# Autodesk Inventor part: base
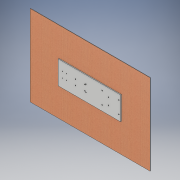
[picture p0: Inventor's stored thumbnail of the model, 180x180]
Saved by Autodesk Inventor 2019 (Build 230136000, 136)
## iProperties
Created: 2021-07
Part Number: base
Material: Generic
Document SubType Name: Modeling
Designer: Avinash
Density: 1 g/cm^3
Appearance: Default
Author: Avinash
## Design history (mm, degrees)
sketch "Sketch1"
  geometry: L1 (0, 0)-(-800, 0); L2 (-800, 0)-(-800, 300); L3 (-800, 300)-(0, 300); L4 (0, 300)-(0, 0)
  constraints: 8 end point, 2 parallel, 1 horizontal, 1 perpendicular
  dimensions: "d0" = 800 distance of L2.end L3.end; "d1" = 300 distance of L1.end L2.end
extrude "Extrusion1" new body sketch "Sketch1" distance "d2" = 10; taper "d3" = 0 deg
sketch "Sketch2"
  geometry: L1 (-30, 225)-(-20, 225); L2 (-20, 225)-(-20, 235); L3 (-20, 235)-(-30, 235); L4 (-30, 235)-(-30, 225); L5 (-30, 65)-(-20, 65); L6 (-20, 65)-(-20, 75); L7 (-20, 75)-(-30, 75); L8 (-30, 75)-(-30, 65); L9 (-800, 0)-(0, 0) reference; L10 (0, 0)-(0, 300) reference; L11 (0, 300)-(-800, 300) reference; L12 (-240, 225)-(-230, 225); L13 (-230, 225)-(-230, 235); L14 (-230, 235)-(-240, 235); L15 (-240, 235)-(-240, 225); L16 (-240, 65)-(-230, 65); L17 (-230, 65)-(-230, 75); L18 (-230, 75)-(-240, 75); L19 (-240, 75)-(-240, 65); L20 (-150, 200)-(-160, 200); L21 (-160, 200)-(-160, 190); L22 (-160, 190)-(-150, 190); L23 (-150, 190)-(-150, 200); L24 (-160, 110)-(-160, 100); L25 (-150, 100)-(-150, 110); L26 (-150, 110)-(-160, 110); L27 (-160, 100)-(-150, 100); L28 (-450, 110)-(-450, 100); L29 (-440, 100)-(-440, 110); L30 (-440, 110)-(-450, 110); L31 (-450, 100)-(-440, 100); L32 (-450, 200)-(-450, 190); L33 (-440, 190)-(-440, 200); L34 (-440, 200)-(-450, 200); L35 (-450, 190)-(-440, 190)
  constraints: 64 end point, 15 parallel, 8 horizontal, 8 perpendicular, 1 vertical
  dimensions: "d4" = 10 distance of L2.end L3.end; "d5" = 10 distance of L3.end L1.start; "d7" = 10 distance of L6.end L7.end; "d8" = 10 distance of L7.end L5.start; "d9" = 65 distance between parallel lines of L9 L5; "d10" = 20 distance between parallel lines of L10 L6; "d11" = 65 distance between parallel lines of L11 L3; "d12" = 10 distance of L13.end L14.end; "d13" = 10 distance of L14.end L12.start; "d14" = 65 distance between parallel lines of L11 L14; "d18" = 220 distance between parallel lines of L15 L2; "d19" = 20 distance between parallel lines of L10 L2; "d20" = 10 distance of L17.end L18.end; "d21" = 10 distance of L18.end L16.start; "d22" = 220 distance between parallel lines of L6 L19; "d23" = 65 distance between parallel lines of L9 L16; "d26" = 10 distance of L20.end L21.end; "d27" = 10 distance of L21.end L22.end; "d28" = 10 distance of L24.start L24.end; "d29" = 10 distance of L24.end L25.start; "d30" = 100 distance between parallel lines of L11 L20; "d31" = 100 distance between parallel lines of L9 L27; "d32" = 10 distance of L28.start L28.end; "d33" = 10 distance of L28.end L29.start; "d34" = 10 distance of L32.start L32.end; "d35" = 10 distance of L32.end L33.start; "d36" = 100 distance between parallel lines of L11 L34; "d37" = 100 distance between parallel lines of L9 L31; "d38" = 300 distance between parallel lines of L32 L23; "d39" = 300 distance between parallel lines of L28 L25; "d41" = 90 distance between parallel lines of L23 L15; "d42" = 90 distance between parallel lines of L25 L19
extrude "Extrusion2" cut sketch "Sketch2" distance "d24" = 50; taper "d25" = 0 deg
extrude "Extrusion3" cut sketch "Sketch2" distance "d43" = 50; taper "d44" = 0 deg
sketch "Sketch3"
  geometry: L1 (-575, 110)-(-585, 110); L2 (-585, 110)-(-585, 120); L3 (-585, 120)-(-575, 120); L4 (-575, 120)-(-575, 110); L5 (-575, 180)-(-585, 180); L6 (-585, 180)-(-585, 190); L7 (-585, 190)-(-575, 190); L8 (-575, 190)-(-575, 180); L9 (-800, 0)-(0, 0) reference; L10 (0, 300)-(-800, 300) reference; L11 (-455, 110)-(-465, 110); L12 (-465, 110)-(-465, 120); L13 (-465, 120)-(-455, 120); L14 (-455, 120)-(-455, 110); L15 (-455, 180)-(-465, 180); L16 (-465, 180)-(-465, 190); L17 (-465, 190)-(-455, 190); L18 (-455, 190)-(-455, 180); L19 (-450, 200)-(-450, 190) reference; L20 (-450, 110)-(-450, 100) reference
  constraints: 32 end point, 8 parallel, 4 horizontal, 4 perpendicular
  dimensions: "d48" = 10 distance of L2.end L3.end; "d49" = 10 distance of L6.end L7.end; "d50" = 10 distance of L5.end L6.end; "d58" = 10 distance of L3.end L1.start; "d60" = 10 distance of L12.end L13.end; "d61" = 10 distance of L13.end L11.start; "d62" = 110 distance between parallel lines of L11 L9; "d63" = 10 distance of L16.end L17.end; "d64" = 10 distance of L17.end L15.start; "d65" = 110 distance between parallel lines of L17 L10; "d66" = 5 distance between parallel lines of L19 L18; "d67" = 5 distance between parallel lines of L20 L14; "d68" = 110 distance between parallel lines of L10 L7; "d69" = 110 distance between parallel lines of L9 L1; "d70" = 130 distance between parallel lines of L6 L18; "d71" = 130 distance between parallel lines of L2 L14
extrude "Extrusion4" cut sketch "Sketch3" distance "d55" = 10; taper "d56" = 0 deg
sketch "Sketch4"
  geometry: L1 (700, 110)-(690, 110); L2 (690, 110)-(690, 115); L3 (690, 115)-(700, 115); L4 (700, 115)-(700, 110); L5 (700, 185)-(690, 185); L6 (690, 185)-(690, 190); L7 (690, 190)-(700, 190); L8 (700, 190)-(700, 185); L9 (750, 110)-(740, 110); L10 (740, 110)-(740, 115); L11 (740, 115)-(750, 115); L12 (750, 115)-(750, 110); L13 (750, 185)-(740, 185); L14 (740, 185)-(740, 190); L15 (740, 190)-(750, 190); L16 (750, 190)-(750, 185); L17 (0, 0)-(800, 0) reference; L18 (800, 300)-(0, 300) reference; L19 (800, 0)-(800, 300) reference
  constraints: 32 end point, 8 parallel, 4 horizontal, 4 perpendicular
  dimensions: "d72" = 5 distance of L1.end L2.end; "d73" = 10 distance of L1.start L1.end; "d74" = 5 distance of L5.end L6.end; "d75" = 10 distance of L5.start L5.end; "d76" = 5 distance of L9.end L10.end; "d77" = 10 distance of L9.start L9.end; "d78" = 5 distance of L13.end L14.end; "d79" = 10 distance of L13.start L13.end; "d80" = 110 distance between parallel lines of L17 L1; "d81" = 110 distance between parallel lines of L18 L7; "d82" = 110 distance between parallel lines of L18 L15; "d83" = 110 distance between parallel lines of L17 L9; "d84" = 60 distance between parallel lines of L2 L12; "d85" = 60 distance between parallel lines of L6 L16; "d90" = 50 distance between parallel lines of L19 L16; "d91" = 50 distance between parallel lines of L19 L12
extrude "Extrusion5" cut sketch "Sketch4" distance "d88" = 10; taper "d89" = 0 deg
sketch "Sketch5"
  geometry: L1 (800, 0)-(0, 0) reference; L2 (800, 0)-(0, 0); L3 (0, 0)-(0, 300); L4 (0, 300)-(800, 300); L5 (800, 300)-(800, 0); L6 (1169.432, -369.432)-(-369.432, -369.432); L7 (-369.432, -369.432)-(-369.432, 669.432); L8 (-369.432, 669.432)-(1169.432, 669.432); L9 (1169.432, 669.432)-(1169.432, -369.432)
  constraints: 16 end point, 2 parallel, 1 horizontal, 1 perpendicular
extrude "Extrusion6" join sketch "Sketch5" distance "d92" = 5; taper "d93" = 0 deg
body "Solid1"
